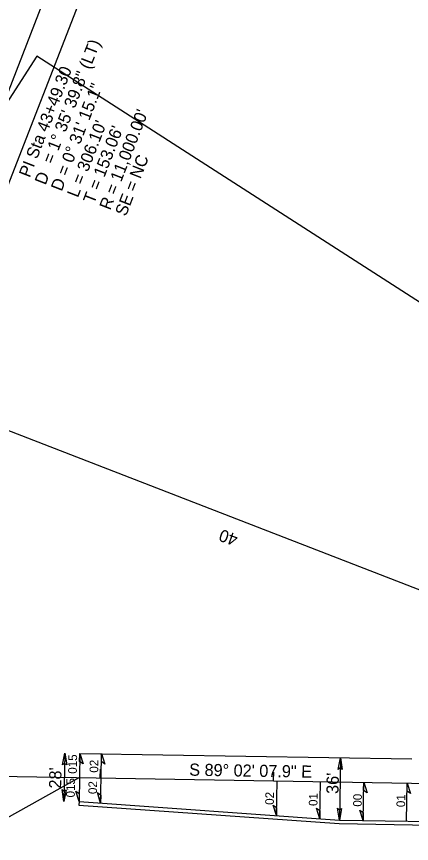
# Model space of a CAD drawing. Extents: x 1974386 to 1979988, y 776712 to 784860.
# Drawn here: x 1976973.5 to 1977201.1, y 780817.6 to 781294.3 of the extents above; entities that cross this region are included whole.
import ezdxf

# ---------------------------------------------------------------- set-up
doc = ezdxf.new("R2010")
doc.units = 0
for name, color, linetype in [('Prop Conc 2ft 6in Curb and Gutter', 7, 'Continuous'), ('Prop Dimension', 7, 'Continuous'), ('Prop Dimension Text', 7, 'Continuous'), ('Prop EOT', 7, 'Continuous'), ('Prop Horizontal Alignment', 7, 'Continuous'), ('Prop Horizontal Alignment Curve and Spiral Data', 7, 'Continuous'), ('Prop Horizontal Alignment Direction Label', 7, 'Continuous'), ('Prop Horizontal Alignment Station Label', 7, 'Continuous'), ('Prop Horizontal Alignment Tick Label', 7, 'Continuous'), ('Prop Horizontal Alignment Tick Small', 7, 'Continuous'), ('Prop Superelevation  Arrow CELL', 7, 'Continuous'), ('Prop Superelevation Label', 7, 'Continuous'), ('Prop Terminator CELL', 7, 'Continuous'), ('Sheet Layout Plan Border', 7, 'Continuous')]:
    doc.layers.add(name, color=color, linetype=linetype)

msp = doc.modelspace()

# ---------------------------------------------------------------- linework, layer by layer
at = {"layer": 'Prop Conc 2ft 6in Curb and Gutter'}
for p, q in [((1977009.49, 780841.78), (1977009.45, 780839.77)), ((1977009.45, 780839.77), (1977159.54, 780829.11)), ((1977159.54, 780829.11), (1977312.1, 780826.54))]:
    msp.add_line(p, q, dxfattribs=at)
at = {"layer": 'Prop Dimension'}
for p, q in [((1977001.3, 780869.69), (1977000.83, 780841.9)), ((1977160.16, 780867.09), (1977159.58, 780831.11))]:
    msp.add_line(p, q, dxfattribs=at)
at = {"layer": 'Prop EOT'}
for p, q in [((1977009.95, 780869.54), (1977009.49, 780841.78)), ((1977009.95, 780869.54), (1977201.38, 780866.41)), ((1977009.49, 780841.78), (1977159.58, 780831.11)), ((1977159.58, 780831.11), (1977312.13, 780828.54))]:
    msp.add_line(p, q, dxfattribs=at)
at = {"layer": 'Prop Horizontal Alignment'}
for p, q in [((1976821.75, 780858.8), (1977201.14, 780852.41)), ((1977201.14, 780852.41), (1977377.51, 780849.45))]:
    msp.add_line(p, q, dxfattribs=at)
at = {"layer": 'Prop Horizontal Alignment Station Label'}
for p, q in [((1976965.67, 781189.17), (1977012.65, 781310.45)), ((1977009.72, 780855.64), (1976835.21, 780758.48))]:
    msp.add_line(p, q, dxfattribs=at)
at = {"layer": 'Prop Horizontal Alignment Tick Small'}
for p, q in [((1977021.72, 780855.43), (1977021.8, 780860.43)), ((1977121.7, 780853.75), (1977121.79, 780858.75))]:
    msp.add_line(p, q, dxfattribs=at)
at = {"layer": 'Prop Superelevation  Arrow CELL'}
for p, q in [((1977022.22, 780855.43), (1977022.45, 780869.42)), ((1977021.97, 780840.9), (1977022.22, 780855.43)), ((1977123.34, 780833.69), (1977123.67, 780853.72)), ((1977148.31, 780831.91), (1977148.67, 780853.3)), ((1977173.3, 780830.88), (1977173.67, 780852.88)), ((1977198.29, 780830.46), (1977198.66, 780852.46))]:
    msp.add_line(p, q, dxfattribs=at)
for points in [[(1977009.95, 780869.54), (1977011.85, 780863.51), (1977009.87, 780864.91)], [(1977022.45, 780869.42), (1977024.35, 780863.39), (1977022.37, 780864.8)], [(1977173.67, 780852.88), (1977175.56, 780846.84), (1977173.59, 780848.25)], [(1977198.66, 780852.46), (1977200.56, 780846.42), (1977198.58, 780847.83)], [(1977009.49, 780841.78), (1977007.59, 780847.82), (1977009.56, 780846.41)], [(1977021.97, 780840.9), (1977020.07, 780846.93), (1977022.05, 780845.52)], [(1977123.34, 780833.69), (1977121.44, 780839.72), (1977123.41, 780838.31)], [(1977148.31, 780831.91), (1977146.41, 780837.94), (1977148.39, 780836.54)], [(1977173.3, 780830.88), (1977171.4, 780836.91), (1977173.37, 780835.5)]]:
    msp.add_lwpolyline(points, close=True, dxfattribs=at)
at = {"layer": 'Prop Terminator CELL'}
for points in [[(1977000.02, 780862.96), (1977001.3, 780869.69), (1977002.38, 780862.88), (1977001.2, 780863.77)], [(1977158.89, 780860.36), (1977160.16, 780867.09), (1977161.25, 780860.28), (1977160.07, 780861.16)], [(1977002.1, 780848.62), (1977000.83, 780841.9), (1976999.74, 780848.7), (1977000.93, 780847.82)], [(1977160.85, 780837.84), (1977159.58, 780831.11), (1977158.49, 780837.92), (1977159.67, 780837.04)]]:
    msp.add_lwpolyline(points, close=True, dxfattribs=at)
at = {"layer": 'Sheet Layout Plan Border'}
for points in [[(1977881.86, 780701.89), (1978387.67, 782007.32), (1977408.59, 782386.68), (1976902.78, 781081.25)], [(1977111.11, 779526.05), (1977868.38, 780703.57), (1976985.24, 781271.52), (1976227.97, 780094)]]:
    msp.add_lwpolyline(points, close=True, dxfattribs=at)

# ---------------------------------------------------------------- texts
at = {"layer": 'Prop Dimension Text'}
for s, p in [("28'", (1976999.16, 780849.21)), ("36'", (1977159.05, 780846.13))]:
    msp.add_text(s, height=7, rotation=88.7641, dxfattribs=at).set_placement(p)
at = {"layer": 'Prop Horizontal Alignment Curve and Spiral Data'}
for s, p in [('= 1%%d 35\' 39.8" (LT)', (1976994.57, 781208.89)), ('PI Sta 43+49.30', (1976981.11, 781201.06)), ('D = 0%%d 31\' 15.1"', (1976999.51, 781193.18)), ("R = 11,000.00'", (1977027.47, 781182.31)), ("L = 306.10'", (1977008.83, 781189.56)), ("T = 153.06'", (1977018.15, 781185.94)), ('SE = NC', (1977036.55, 781178.79)), ('D', (1976990.19, 781196.81))]:
    msp.add_text(s, height=7, rotation=68.7521, dxfattribs=at).set_placement(p)
at = {"layer": 'Prop Horizontal Alignment Direction Label'}
msp.add_text('S 89%%d 02\' 07.9" E', height=7, rotation=359.0355, dxfattribs=at).set_placement((1977072.98, 780856.72))
at = {"layer": 'Prop Horizontal Alignment Tick Label'}
msp.add_text('40', height=7, rotation=160.6265, dxfattribs=at).set_placement((1977101.64, 780995.48))
at = {"layer": 'Prop Superelevation Label'}
for s, p in [('015', (1977008.22, 780857.78)), ('02', (1977020.57, 780858.39)), ('015', (1977007.04, 780844.13)), ('02', (1977019.84, 780846.08)), ('02', (1977121.82, 780839.87)), ('01', (1977146.93, 780839.2)), ('00', (1977172.47, 780838.8)), ('01', (1977197.46, 780838.54))]:
    msp.add_text(s, height=5, rotation=89.0355, dxfattribs=at).set_placement(p)

doc.saveas('drawing.dxf')
